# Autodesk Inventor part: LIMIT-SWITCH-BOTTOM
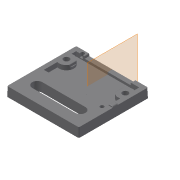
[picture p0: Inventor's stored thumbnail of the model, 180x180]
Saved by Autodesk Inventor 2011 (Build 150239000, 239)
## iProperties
Created: 2007-08
Part Number: LIMIT-SWITCH-BOTTOM
Material: ABS Plastic
Document SubType Name: Modeling
Density: 1.06 g/cm^3
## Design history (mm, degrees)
feature "Base1"
workplane "Work Plane1"
body "Solid1"
